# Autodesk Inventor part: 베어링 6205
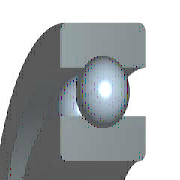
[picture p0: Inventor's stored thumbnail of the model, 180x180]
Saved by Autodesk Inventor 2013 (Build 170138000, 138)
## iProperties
IsCustomPart: 1
Company: 한국ATC센터
Created: 2014-11
Part Number: 베어링 6205
Material: 강, 연강
Description: 깊은 그루브 볼 베어링
Document SubType Name: Modeling
Standard: KS B 2023
Designer: KYOUNG IL JANG
Standards Organization: KS
Language: ko-KR
Size Designation: 6205 - 25 x 52 x 15
Categories: <MemberInstance><Categories><Category DisplayName="샤프트 부품" InternalName="7f7aeb1f-a693-4053-b835-cee3144e0d98" Mnemonic="SHFT"><Category DisplayName="베어링" Inter
Density: 7.86 g/cm^3
Mass: 129.543 g
Surface Area: 107.326 cm^2
Volume: 16.4813 cm^3
Author: KYOUNG IL JANG
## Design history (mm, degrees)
sketch "스케치" dims "d0" = 7.02 (= -0.26 x WD + 0.26 x BD)
  geometry: L1 (3.99, 19.25)-(11.01, 19.25); L2 (7.5, 19.25)-(7.5, 15.74); L3 (7.5, 19.25)-(7.5, 22.76); L4 (4.892, 16.901)-(0, 16.901); L5 (0, 12.5)-(15, 12.5); L6 (4.892, 21.599)-(0, 21.599); L7 (0, 26)-(15, 26); L8 (15, 12.5)-(15, 16.901); L9 (10.108, 16.901)-(15, 16.901); L10 (10.108, 21.599)-(15, 21.599); L11 (15, 26)-(15, 21.599); L12 (-1.4, 0)-(8.4, 0) reference; L13 (0, -0.3)-(0, 5.3) reference
  constraints: 22 end point, 4 point on line, 2 collinear, 2 perpendicular, 2 symmetric about line, 1 midpoint, 1 parallel, 14 other
  dimensions: "d9" = 25 diameter of L5 L12 (= WD); "d11" = 52 diameter of L7 L12 (= BD); "d12" = 15 distance between parallel lines of L8 L13 (= KB); "d13" = 33.802 diameter of L9 L12 (= 0.326 x BD + 0.674 x WD)
revolve "본체" stored, may be unused: angle "d6" = 90 deg
revolve "볼" stored, may be unused: angle "d7" = 90 deg
pattern_circular "IDS_ARRAYBALL[SIMPL:T]" dims angle "d3" = 360 deg
body "Solid1"
fillet "모깎기1" dims "d1" = 1 (= KRS)
other parameters: "WD" = 25 [user parameter; used in 5 equation terms], "BD" = 52 [user parameter; used in 5 equation terms], "KB" = 15 [user parameter; used in 1 equation term], "KRS" = 1 [user parameter; used in 1 equation term], "d4" = 0, "d5" = 0, "d8" = 0, "d14" = 0, "d15" = 0, "BBA" = 0 [user parameter], "BC0" = 7800000 [user parameter], "BC" = 1.4e+07 [user parameter], "BR" = 26 (= 0.5 x BD) [user parameter], "WR" = 12.5 (= 0.5 x WD) [user parameter]
